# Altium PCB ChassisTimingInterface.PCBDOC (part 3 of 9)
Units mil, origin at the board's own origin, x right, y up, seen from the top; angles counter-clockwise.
Board outline 7007.87 x 4368.85 mil, 10 copper layers (Top Layer, Int1 (GND), Int2 (Sign), Int3 (Sign), Int4 (PWR), Int5 (GND), Int6 (Sign), Int7 (Sign), Int8 (GND), Bottom Layer), stack 54.89 mil thick; 537 components, 525 nets, 2288 pads, 1306 vias.
Unrouted connection lines stored in the file: 373.
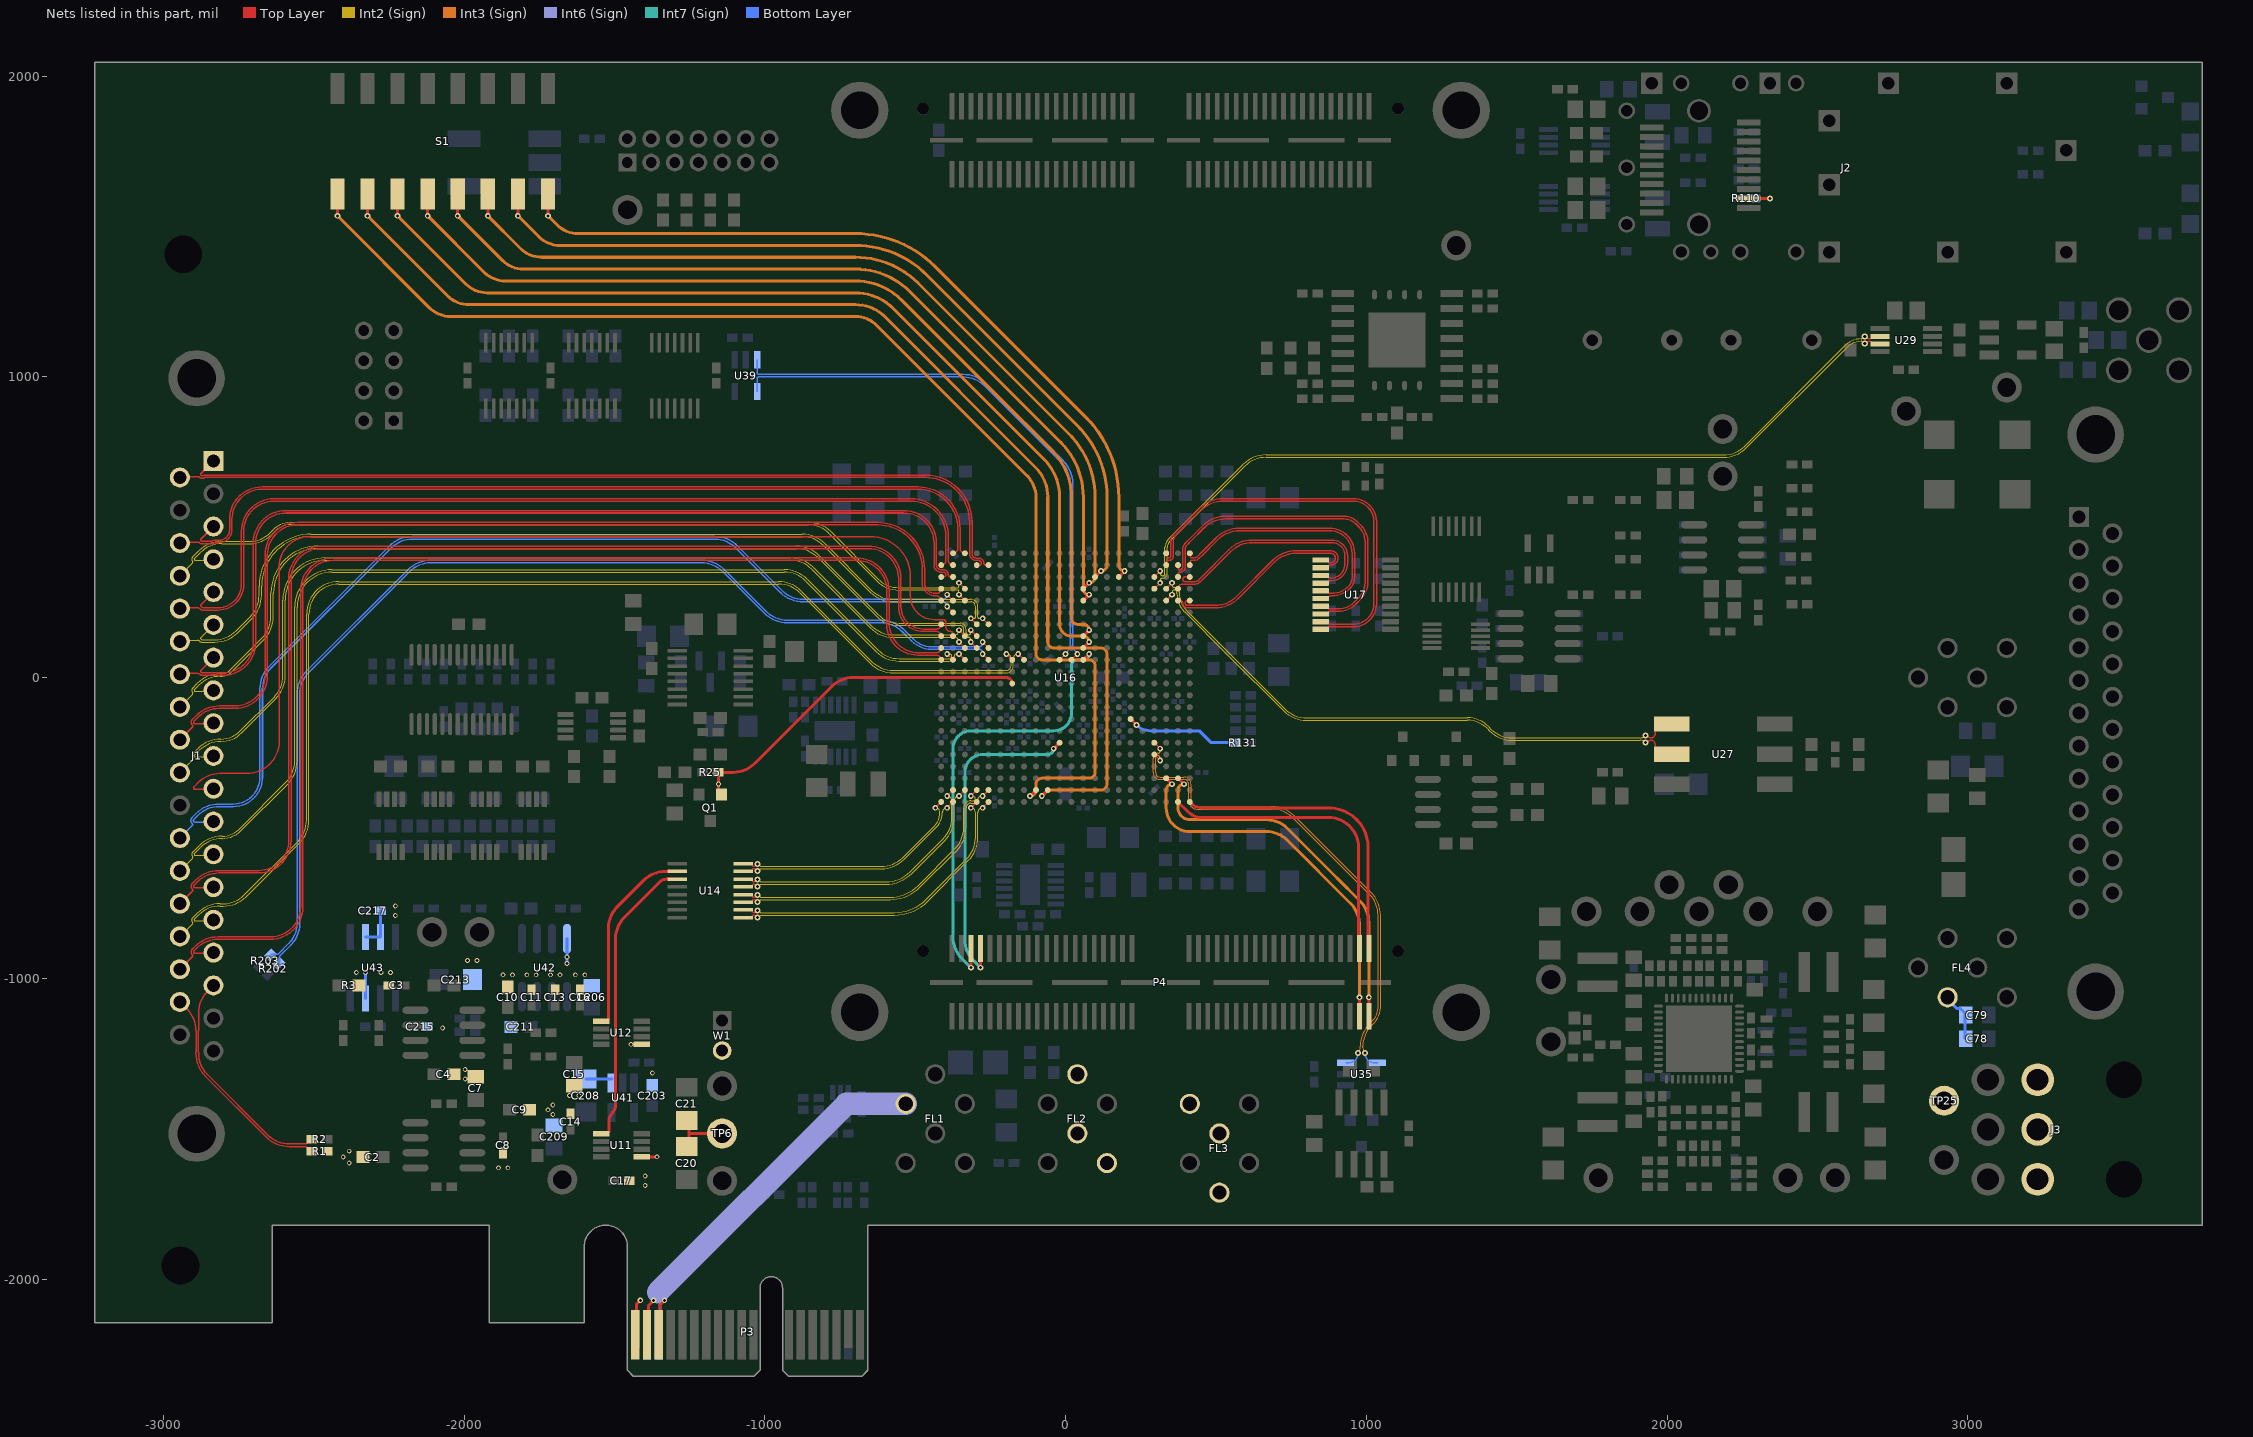
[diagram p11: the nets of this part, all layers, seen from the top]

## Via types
v1: diameter 19, hole 10, Top Layer to Bottom Layer, tented both sides, 667 vias
v2: diameter 20, hole 10, Top Layer to Bottom Layer, tented both sides, 248 vias
v3: diameter 16, hole 10, Top Layer to Bottom Layer, tented both sides, 191 vias
v4: diameter 12, hole 6, Top Layer to Bottom Layer, tented both sides, 85 vias
v5: diameter 19.68, hole 10, Top Layer to Bottom Layer, tented both sides, 50 vias
v6: diameter 17.72, hole 10, Top Layer to Bottom Layer, tented both sides, 19 vias
v7: diameter 19, hole 10, Top Layer to Bottom Layer, 15 vias
v8: diameter 23.62, hole 10, Top Layer to Bottom Layer, tented both sides, 14 vias
v9: diameter 20, hole 10, Top Layer to Bottom Layer, 11 vias
v10: diameter 16, hole 10, Top Layer to Bottom Layer, 3 vias
v11: diameter 22, hole 12, Top Layer to Bottom Layer, tented both sides, 2 vias
v12: diameter 19.02, hole 10, Top Layer to Bottom Layer, tented both sides, 1 vias

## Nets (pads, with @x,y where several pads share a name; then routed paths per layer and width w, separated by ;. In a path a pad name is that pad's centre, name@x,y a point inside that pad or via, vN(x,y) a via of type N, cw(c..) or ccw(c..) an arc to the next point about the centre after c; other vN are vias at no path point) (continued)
BACKPLANE.CLK1_P: J1.11 U16.B15 | length 3536.1
  Top Layer w5: J1.11@-2832.87,-369.88 cw(c-2837.97,-364.78) -2837.97,-371.99 -2894.34,-371.99 cw(c-2894.34,-366.99) -2897.88,-370.53 cw(c-2894.34,-366.99) -2899.34,-366.99 cw(c-2894.34,-366.99) -2897.88,-363.46 -2882.6,-348.19 cw(c-2811.89,-418.9) -2811.89,-318.9 -2722.17,-318.9 ccw(c-2722.17,-210.9) -2614.17,-210.9 -2614.17,368.5 cw(c-2514.17,368.5) -2514.17,468.5 -647.75,468.5 cw(c-647.75,336.5) -515.75,336.5 -515.75,271.53 ccw(c-436.92,271.53) -436.92,192.7 -406.92,192.7 cw(c-406.92,183.55) -397.77,183.55 -397.77,168.53 ccw(c-382.72,168.53) -382.72,153.48 cw(c-382.72,144.78) -374.02,144.78 U16.B15@-374.02,137.8
BACKPLANE.CLK2_N: J1.29 U16.C15 | length 3214.3
  Top Layer w5: v1(-354.33,157.48) U16.C15@-334.65,137.8
  Int2 (Sign) w3: J1.29@-2944.69,-315.35 -2902.12,-272.79 ccw(c-2904.24,-270.67) -2901.24,-270.67 ccw(c-2904.24,-270.67) -2902.12,-268.54 ; -2905.34,-260.8 ccw(c-2894.42,-260.8) -2902.14,-268.52 ; -2905.34,-260.76 cw(c-2894.36,-260.76) -2902.13,-253 -2885.33,-236.2 cw(c-2809.03,-312.5) -2809.03,-204.6 ccw(c-2809.03,-114.05) -2745.01,-178.08 -2631.78,-64.85 ccw(c-2702.49,5.86) -2602.49,5.86 -2602.49,257.76 cw(c-2462.49,257.76) -2462.49,397.76 -914.9,397.76 cw(c-914.9,289.85) -838.6,366.16 -643.53,171.09 ccw(c-572.82,241.8) -572.82,141.8 -536.42,141.8 -370.02,141.8 ccw(c-370.02,157.48) v1(-354.33,157.48)
BACKPLANE.CLK2_P: J1.10 U16.C14 | length 3195.2
  Top Layer w5: v1(-354.33,118.11) U16.C14@-334.65,98.43
  Int2 (Sign) w3: J1.10@-2832.87,-260.83 cw(c-2839.97,-253.73) -2839.97,-263.77 -2894.34,-263.77 cw(c-2894.34,-260.77) -2896.46,-262.89 cw(c-2894.34,-260.77) -2897.34,-260.77 cw(c-2894.34,-260.77) -2896.46,-258.65 -2879.7,-241.89 cw(c-2808.99,-312.6) -2808.99,-212.6 ccw(c-2808.99,-114.15) -2739.38,-183.76 -2626.09,-70.48 ccw(c-2702.39,5.82) -2594.49,5.82 -2594.49,257.76 cw(c-2462.49,257.76) -2462.49,389.76 -914.94,389.76 cw(c-914.94,289.76) -844.23,360.47 -649.17,165.41 ccw(c-572.84,241.74) -572.99,133.8 ccw(c-572.84,241.74) -572.84,133.8 -536.42,133.8 -370.02,133.8 cw(c-370.02,118.11) v1(-354.33,118.11)
BACKPLANE.CLK3_N: J1.28 U16.A19 | length 3274.8
  Top Layer w5: J1.28@-2944.69,-206.3 -2903.53,-165.15 ccw(c-2907.07,-161.61) -2902.07,-161.61 ccw(c-2907.07,-161.61) -2903.53,-158.08 ; -2903.57,-158.04 cw(c-2894.46,-148.93) -2907.34,-148.93 -2907.34,-148.81 cw(c-2894.51,-148.81) -2903.58,-139.74 -2889.81,-125.97 cw(c-2813.51,-202.26) -2813.51,-94.36 -2761.54,-94.36 ccw(c-2761.54,5.64) -2661.54,5.64 -2661.54,407.87 cw(c-2553.54,407.87) -2553.54,515.87 -624.38,515.87 cw(c-624.38,359.87) -468.38,359.87 -468.38,314.93 ccw(c-433.04,314.93) -433.04,279.59 -429.07,279.59 ccw(c-429.07,295.28) U16.A19@-413.39,295.28
BACKPLANE.CLK3_P: J1.9 U16.A18 | length 3255.9
  Top Layer w5: J1.9@-2832.87,-151.77 cw(c-2837.97,-146.67) -2837.97,-153.88 -2894.34,-153.88 cw(c-2894.34,-148.88) -2897.88,-152.42 cw(c-2894.34,-148.88) -2899.34,-148.88 cw(c-2894.34,-148.88) -2897.88,-145.35 -2884.18,-131.65 cw(c-2813.47,-202.36) -2813.47,-102.36 -2761.54,-102.36 ccw(c-2761.54,5.64) -2653.54,5.64 -2653.54,407.87 cw(c-2553.54,407.87) -2553.54,507.87 -624.38,507.87 cw(c-624.38,359.87) -476.38,359.87 -476.38,314.93 ccw(c-433.04,314.93) -433.04,271.59 -429.07,271.59 cw(c-429.07,255.91) U16.A18@-413.39,255.91
BACKPLANE.CLK4_N: J1.27 U16.D15 | length 3113.3
  Top Layer w5: v1(-314.96,157.48) U16.D15@-295.28,137.8
  Int2 (Sign) w3: J1.27@-2944.69,-97.24 -2902.12,-54.68 ccw(c-2904.24,-52.56) -2901.24,-52.56 ccw(c-2904.24,-52.56) -2902.12,-50.43 ; -2905.34,-42.69 ccw(c-2894.42,-42.69) -2902.14,-50.41 ; -2905.34,-42.65 cw(c-2894.36,-42.65) -2902.13,-34.89 -2886.91,-19.67 cw(c-2810.61,-95.96) -2810.61,11.94 ccw(c-2810.61,58.76) -2777.5,25.65 -2671.15,132 ccw(c-2741.86,202.71) -2641.86,202.71 -2641.86,281.13 cw(c-2485.86,281.13) -2485.86,437.13 -895.22,437.13 cw(c-895.22,329.22) -818.91,405.53 -623.9,210.52 ccw(c-553.19,281.23) -553.19,181.23 -536.42,181.23 -350.52,181.23 cw(c-350.52,161.42) -330.71,161.42 -330.71,149.67 ccw(c-322.83,149.67) -322.83,141.8 ccw(c-322.83,149.67) -314.96,149.67 v1(-314.96,157.48)
BACKPLANE.CLK4_P: J1.8 U16.D14 | length 3094.1
  Top Layer w5: v1(-314.96,118.11) U16.D14@-295.28,98.43
  Int2 (Sign) w3: J1.8@-2832.87,-42.72 cw(c-2839.97,-35.62) -2839.97,-45.66 -2894.34,-45.66 cw(c-2894.34,-42.66) -2896.46,-44.78 cw(c-2894.34,-42.66) -2897.34,-42.66 cw(c-2894.34,-42.66) -2896.46,-40.53 -2881.28,-25.35 cw(c-2810.57,-96.06) -2810.57,3.94 ; -2810.52,3.94 ccw(c-2810.52,58.56) -2771.9,19.94 -2665.39,126.45 ccw(c-2741.5,202.57) -2633.86,202.57 -2633.86,281.13 cw(c-2485.86,281.13) -2485.86,429.13 -1354.33,429.13 -895.25,429.13 cw(c-895.25,329.13) -824.54,399.84 -629.54,204.84 ccw(c-553.22,281.17) -553.36,173.23 ccw(c-553.22,281.17) -553.22,173.23 -536.42,173.23 -350.52,173.23 cw(c-350.52,161.42) -338.71,161.42 -338.71,149.67 ccw(c-322.83,149.67) -322.83,133.8 cw(c-322.83,125.92) -314.96,125.92 v1(-314.96,118.11)
BACKPLANE.CLK5_N: J1.26 U16.A20 | length 3167.9
  Top Layer w5: J1.26@-2944.69,11.81 cw(c-2939.59,6.71) -2939.59,13.92 -2885.51,13.92 cw(c-2885.51,3.38) -2878.06,10.84 ccw(c-2870.61,18.29) -2870.61,7.75 -2800.91,7.75 ccw(c-2800.91,115.75) -2692.91,115.75 -2692.91,447.24 cw(c-2592.91,447.24) -2592.91,547.24 -537.13,547.24 cw(c-537.13,447.24) -437.13,447.24 -437.13,374.02 ccw(c-413.45,374.02) -413.45,350.33 -405.57,350.33 cw(c-405.57,342.46) -397.7,342.46 cw(c-405.51,342.46) -405.51,334.65 U16.A20@-413.39,334.65
BACKPLANE.CLK5_P: J1.7 U16.B20 | length 3174.3
  Top Layer w5: J1.7@-2832.87,66.34 -2874.03,25.19 ccw(c-2870.49,21.65) -2875.49,21.65 ccw(c-2870.49,21.65) -2874.03,18.12 ccw(c-2868.31,23.83) -2868.31,15.75 -2800.91,15.75 ccw(c-2800.91,115.75) -2700.91,115.75 -2700.91,447.24 cw(c-2592.91,447.24) -2592.91,555.24 -537.13,555.24 cw(c-537.13,447.24) -429.13,447.24 -429.13,374.02 ccw(c-413.45,374.02) -413.45,358.33 -405.57,358.33 cw(c-405.57,342.46) -389.7,342.46 ccw(c-381.89,342.46) -381.89,334.65 U16.B20@-374.02,334.65
BACKPLANE.CLK6_N: J1.25 U16.D16 | length 3024.6
  Top Layer w5: v1(-314.96,196.85) U16.D16@-295.28,177.17
  Int2 (Sign) w3: J1.25@-2944.69,120.87 cw(c-2937.59,113.77) -2937.59,123.81 -2886.09,123.81 cw(c-2886.09,113.87) -2879.07,120.9 ccw(c-2872.04,127.92) -2872.04,117.98 -2828.78,117.98 ccw(c-2828.78,225.89) -2752.48,149.59 -2704.83,197.24 ccw(c-2781.13,273.54) -2673.23,273.54 -2673.23,304.5 cw(c-2509.23,304.5) -2509.23,468.5 -875.57,468.5 cw(c-875.57,368.5) -804.86,439.21 -649.23,283.58 ccw(c-572.9,359.91) -573.05,251.97 ccw(c-572.9,359.91) -572.9,251.97 -536.42,251.97 -314.96,251.97 cw(c-314.96,236.28) -299.28,236.28 -299.28,200.79 cw(c-303.21,200.79) -303.21,196.85 v1(-314.96,196.85)
BACKPLANE.CLK6_P: J1.6 U16.E16 | length 3031.2
  Top Layer w5: v1(-275.59,196.85) U16.E16@-255.91,177.17
  Int2 (Sign) w3: J1.6@-2832.87,175.39 -2875.44,132.83 ccw(c-2873.32,130.71) -2876.32,130.71 ccw(c-2873.32,130.71) -2875.44,128.58 ccw(c-2869.16,134.86) -2869.16,125.98 -2828.82,125.98 ccw(c-2828.82,225.98) -2758.11,155.27 -2710.52,202.87 ccw(c-2781.23,273.58) -2681.23,273.58 -2681.23,304.5 cw(c-2509.23,304.5) -2509.23,476.5 -875.53,476.5 cw(c-875.53,368.59) -799.23,444.9 -643.59,289.26 ccw(c-572.88,359.97) -572.88,259.97 -536.42,259.97 -314.96,259.97 cw(c-314.96,236.28) -291.28,236.28 -291.28,200.79 ccw(c-287.34,200.79) -287.34,196.85 v1(-275.59,196.85)
BACKPLANE.CLK7_N: J1.24 U16.A21 | length 3003.7
  Top Layer w5: J1.24@-2944.69,229.92 cw(c-2939.59,224.82) -2939.59,232.03 -2886.63,232.03 cw(c-2886.63,218.8) -2877.27,228.16 ccw(c-2867.92,237.51) -2867.92,224.28 -2818.86,224.28 ccw(c-2818.86,310.98) -2732.16,310.98 -2732.16,486.68 cw(c-2632.16,486.68) -2632.16,586.68 -513.7,586.68 cw(c-513.7,470.68) -397.7,470.68 -397.7,452.76 -397.7,389.7 cw(c-413.39,389.7) U16.A21@-413.39,374.02
BACKPLANE.CLK7_P: J1.5 U16.B21 | length 3010.1
  Top Layer w5: J1.5@-2832.87,284.45 -2874.03,243.3 ccw(c-2870.49,239.76) -2875.49,239.76 ccw(c-2870.49,239.76) -2874.03,236.23 ccw(c-2864.51,245.74) -2864.51,232.28 -2818.9,232.28 ccw(c-2818.9,311.02) -2740.16,311.02 -2740.16,486.68 cw(c-2632.16,486.68) -2632.16,594.68 -513.7,594.68 cw(c-513.7,470.68) -389.7,470.68 -389.7,452.76 -389.7,389.7 ccw(c-374.02,389.7) U16.B21@-374.02,374.02
BACKPLANE.CLK8_N: J1.23 U16.C19 | length 2788.3
  Top Layer w5: v1(-354.33,314.96) U16.C19@-334.65,295.28
  Int2 (Sign) w3: J1.23@-2944.69,338.98 -2902.12,381.54 ccw(c-2904.24,383.66) -2901.24,383.66 ccw(c-2904.24,383.66) -2902.12,385.79 ; -2905.34,393.53 ccw(c-2894.42,393.53) -2902.14,385.81 ; -2905.34,393.57 cw(c-2894.36,393.57) -2902.13,401.34 -2882.18,421.28 cw(c-2805.88,344.98) -2805.88,452.88 -2714.52,452.88 ccw(c-2714.52,552.88) -2643.81,482.17 -2633.83,492.15 cw(c-2576.56,434.88) -2576.56,515.87 -855.79,515.87 cw(c-855.79,408.11) -779.59,484.31 -623.78,328.5 ccw(c-553.07,399.21) -553.07,299.21 -549.1,299.21 -549.03,299.28 -536.42,299.28 -356.09,299.28 -354.33,301.03 v1(-354.33,314.96)
BACKPLANE.CLK8_P: J1.4 U16.C18 | length 2769.1
  Top Layer w5: v1(-354.33,275.59) U16.C18@-334.65,255.91
  Int2 (Sign) w3: J1.4@-2832.87,393.5 cw(c-2839.97,400.6) -2839.97,390.56 -2894.34,390.56 cw(c-2894.34,393.56) -2896.46,391.44 cw(c-2894.34,393.56) -2897.34,393.56 cw(c-2894.34,393.56) -2896.46,395.69 -2876.55,415.59 cw(c-2805.84,344.88) -2805.84,444.88 -2714.48,444.88 ccw(c-2714.48,552.78) -2638.19,476.49 -2628.2,486.47 cw(c-2576.53,434.79) -2576.53,507.87 -855.88,507.87 cw(c-855.88,407.87) -785.17,478.58 -629.42,322.83 ccw(c-553.09,399.16) -553.09,291.21 -545.15,291.21 -545.09,291.28 -536.42,291.28 -356.09,291.28 -354.33,289.52 v1(-354.33,275.59)
BACKPLANE.CLK9_N: J1.22 U16.B22 | length 2870.1
  Top Layer w5: J1.22@-2944.69,448.03 cw(c-2939.59,442.93) -2939.59,450.14 -2884.88,450.14 cw(c-2884.88,441.14) -2878.51,447.51 ccw(c-2872.15,453.87) -2872.15,444.87 -2840.36,444.87 ccw(c-2840.36,456.23) -2832.33,448.2 ; -2832.31,448.21 cw(c-2830.86,446.76) -2830.86,448.82 -2814.83,448.82 ccw(c-2814.83,492.13) -2771.53,492.13 -2771.53,526.05 cw(c-2671.53,526.05) -2671.53,626.05 -490.33,626.05 cw(c-490.33,494.05) -358.33,494.05 -358.33,452.76 -358.33,429.07 cw(c-374.02,429.07) U16.B22@-374.02,413.39
BACKPLANE.CLK9_P: J1.3 U16.C22 | length 2876.4
  Top Layer w5: -2837.97,453.87 cw(c-2840.39,456.29) -2840.39,452.87 -2870.49,452.87 cw(c-2870.49,457.87) -2874.03,454.34 cw(c-2870.49,457.87) -2875.49,457.87 cw(c-2870.49,457.87) -2874.03,461.41 J1.3@-2832.87,502.56 ; -2837.94,453.9 cw(c-2830.89,446.85) -2830.89,456.82 -2814.83,456.82 ccw(c-2814.83,492.13) -2779.53,492.13 -2779.53,526.05 cw(c-2671.53,526.05) -2671.53,634.05 -490.33,634.05 cw(c-490.33,494.05) -350.33,494.05 -350.33,452.76 -350.33,429.07 ccw(c-334.65,429.07) U16.C22@-334.65,413.39
BACKPLANE.CS_N: J1.32 U16.B13 | length 3492.2
  Top Layer w5: v1(-393.7,78.74) U16.B13@-374.02,59.06
  Int2 (Sign) w3: J1.32@-2944.69,-642.52 -2902.12,-599.95 ccw(c-2904.24,-597.83) -2901.24,-597.83 ccw(c-2904.24,-597.83) -2902.12,-595.71 ; -2902.14,-595.69 cw(c-2894.42,-587.96) -2905.34,-587.96 cw(c-2894.36,-587.92) -2902.13,-580.16 -2881,-559.04 cw(c-2804.7,-635.33) -2804.7,-527.43 ccw(c-2804.7,-447.34) -2748.07,-503.97 -2592.41,-348.31 ccw(c-2663.12,-277.6) -2563.12,-277.6 -2563.12,234.39 cw(c-2439.12,234.39) -2439.12,358.39 -934.59,358.39 cw(c-934.59,250.48) -858.28,326.79 -623.78,92.28 ccw(c-553.07,162.99) -553.07,62.99 -536.42,62.99 -385.89,62.99 ccw(c-385.89,70.87) -378.02,70.87 ccw(c-385.89,70.87) -385.89,78.74 v1(-393.7,78.74)
BACKPLANE.CS_P: J1.13 U16.C13 | length 3485.6
  Top Layer w5: v1(-354.33,78.74) U16.C13@-334.65,59.06
  Int2 (Sign) w3: J1.13@-2832.87,-587.99 cw(c-2839.97,-580.89) -2839.97,-590.93 -2894.34,-590.93 cw(c-2894.34,-587.93) -2896.46,-590.05 cw(c-2894.34,-587.93) -2897.34,-587.93 cw(c-2894.34,-587.93) -2896.46,-585.81 -2875.37,-564.72 cw(c-2804.66,-635.43) -2804.66,-535.43 ccw(c-2804.66,-447.44) -2742.44,-509.66 -2586.72,-353.94 ccw(c-2663.02,-277.64) -2555.12,-277.64 -2555.12,234.39 cw(c-2439.12,234.39) -2439.12,350.39 -934.62,350.39 cw(c-934.62,250.39) -863.91,321.1 -629.42,86.61 ccw(c-553.09,162.93) -553.09,54.99 -536.42,54.99 -385.89,54.99 ccw(c-385.89,70.87) -370.02,70.87 cw(c-362.14,70.87) -362.14,78.74 v1(-354.33,78.74)
BACKPLANE.DIN_N: J1.35 U16.A14 | length 3995
  Top Layer w5: J1.35@-2944.69,-969.68 -2903.53,-928.53 ccw(c-2907.07,-925) -2902.07,-925 ccw(c-2907.07,-925) -2903.53,-921.46 cw(c-2894.46,-912.32) -2907.34,-912.32 -2907.34,-912.2 cw(c-2894.51,-912.2) -2903.58,-903.13 -2894.14,-893.68 cw(c-2817.84,-969.98) -2817.84,-862.08 -2643.43,-862.08 ccw(c-2643.43,-762.08) -2543.43,-762.08 -2543.43,289.76 cw(c-2435.43,289.76) -2435.43,397.76 -694.49,397.76 cw(c-694.49,289.76) -586.49,289.76 -586.49,181.04 ccw(c-488.19,181.04) -488.19,82.74 -452.76,82.74 -429.07,82.74 ccw(c-429.07,98.43) U16.A14@-413.39,98.43
BACKPLANE.DIN_P: J1.16 U16.A13 | length 3977.4
  Top Layer w5: J1.16@-2832.87,-915.16 cw(c-2837.97,-910.06) -2837.97,-917.27 -2894.34,-917.27 cw(c-2894.34,-912.27) -2897.88,-915.8 cw(c-2894.34,-912.27) -2899.34,-912.27 cw(c-2894.34,-912.27) -2897.88,-908.73 -2888.51,-899.37 cw(c-2817.8,-970.08) -2817.8,-870.08 -2643.43,-870.08 ccw(c-2643.43,-762.08) -2535.43,-762.08 -2535.43,289.76 cw(c-2435.43,289.76) -2435.43,389.76 -694.49,389.76 cw(c-694.49,289.76) -594.49,289.76 -594.49,177.73 ccw(c-491.5,177.73) -491.5,74.74 -452.76,74.74 -429.07,74.74 cw(c-429.07,59.06) U16.A13@-413.39,59.06
BACKPLANE.DOUT_N: J1.34 U16.G13 | length 3894
  Top Layer w5: v1(-196.85,78.74) U16.G13@-177.17,59.06
  Int2 (Sign) w3: J1.34@-2944.69,-860.63 -2902.12,-818.06 ccw(c-2904.24,-815.94) -2901.24,-815.94 ccw(c-2904.24,-815.94) -2902.12,-813.82 ; -2905.34,-806.07 ccw(c-2894.42,-806.07) -2902.14,-813.8 ; -2905.34,-806.03 cw(c-2894.36,-806.03) -2902.13,-798.27 -2887.3,-783.45 cw(c-2811,-859.74) -2811,-751.84 -2801.14,-751.84 ccw(c-2801.14,-651.84) -2730.43,-722.55 -2553.04,-545.16 ccw(c-2623.75,-474.45) -2523.75,-474.45 -2523.75,211.02 cw(c-2415.75,211.02) -2415.75,319.02 -954.25,319.02 cw(c-954.25,211.17) -877.98,287.43 -643.46,52.91 ccw(c-572.75,123.62) -572.75,23.62 -536.42,23.62 -196.91,23.62 ccw(c-196.91,39.37) -181.17,39.37 -181.17,63.06 ccw(c-196.85,63.06) v1(-196.85,78.74)
BACKPLANE.DOUT_P: J1.15 U16.H13 | length 3887.4
  Top Layer w5: v1(-157.48,78.74) U16.H13@-137.8,59.06
  Int2 (Sign) w3: J1.15@-2832.87,-806.1 cw(c-2839.97,-799) -2839.97,-809.04 -2894.34,-809.04 cw(c-2894.34,-806.04) -2896.46,-808.16 cw(c-2894.34,-806.04) -2897.34,-806.04 cw(c-2894.34,-806.04) -2896.46,-803.92 -2881.67,-789.13 cw(c-2810.96,-859.84) -2810.96,-759.84 -2801.1,-759.84 ccw(c-2801.1,-651.94) -2724.8,-728.24 -2547.35,-550.79 ccw(c-2623.65,-474.49) -2515.75,-474.49 -2515.75,211.02 cw(c-2415.75,211.02) -2415.75,311.02 -954.31,311.02 cw(c-954.31,211.02) -883.6,281.73 -649.1,47.24 ccw(c-572.78,123.56) -572.78,15.62 -536.42,15.62 -196.91,15.62 ccw(c-196.91,39.37) -173.17,39.37 -173.17,63.06 cw(c-157.48,63.06) v1(-157.48,78.74)
BACKPLANE.SCLK_N: J1.33 U16.A16 | length 3785.6
  Top Layer w5: J1.33@-2944.69,-751.57 -2903.53,-710.42 ccw(c-2907.07,-706.89) -2902.07,-706.89 ccw(c-2907.07,-706.89) -2903.53,-703.35 ; -2903.57,-703.32 cw(c-2894.46,-694.21) -2907.34,-694.21 -2907.34,-694.09 cw(c-2894.51,-694.09) -2903.58,-685.02 -2891.78,-673.21 cw(c-2815.48,-749.51) -2815.48,-641.61 -2682.8,-641.61 ccw(c-2682.8,-541.61) -2582.8,-541.61 -2582.8,329.13 cw(c-2474.8,329.13) -2474.8,437.13 -655.24,437.13 cw(c-655.24,329.13) -547.24,329.13 -547.24,236.22 ccw(c-472.5,236.22) -472.5,161.48 -452.76,161.48 -429.07,161.48 ccw(c-429.07,177.17) U16.A16@-413.39,177.17
BACKPLANE.SCLK_P: J1.14 U16.A15 | length 3766.6
  Top Layer w5: J1.14@-2832.87,-697.05 cw(c-2837.97,-691.95) -2837.97,-699.16 -2894.34,-699.16 cw(c-2894.34,-694.16) -2897.88,-697.69 cw(c-2894.34,-694.16) -2899.34,-694.16 cw(c-2894.34,-694.16) -2897.88,-690.62 -2886.15,-678.9 cw(c-2815.44,-749.61) -2815.44,-649.61 -2682.8,-649.61 ccw(c-2682.8,-541.61) -2574.8,-541.61 -2574.8,329.13 cw(c-2474.8,329.13) -2474.8,429.13 -655.24,429.13 cw(c-655.24,329.13) -555.24,329.13 -555.24,236.22 ccw(c-472.5,236.22) -472.5,153.48 -452.76,153.48 -429.07,153.48 cw(c-429.07,137.8) U16.A15@-413.39,137.8
BACKPLANE.X1_N: R203.1 U16.E14 | length 3534
  Top Layer w5: v1(-275.59,118.11) U16.E14@-255.91,98.43
  Bottom Layer w5: R203.1@-2643.32,-922.85 cw(c-2636.6,-929.57) -2636.6,-920.07 -2624.94,-920.07 ccw(c-2623.34,-918.47) -2623.34,-920.73 ccw(c-2623.34,-911.99) -2617.16,-918.17 -2581.78,-882.79 ccw(c-2646.15,-818.42) -2555.12,-818.42 -2555.12,-54.57 cw(c-2446.81,-54.57) -2523.39,22.01 -2186.64,358.77 cw(c-2110.05,282.18) -2110.05,390.49 -1210.62,390.49 cw(c-1210.62,282.1) -1133.98,358.74 -995.11,219.87 ccw(c-924.4,290.58) -924.4,190.58 -613.43,190.58 cw(c-613.43,82.19) -536.79,158.83 -505.99,128.04 ccw(c-444.88,189.15) -444.88,102.73 -287.4,102.73 ccw(c-287.4,114.54) -275.59,114.54 v1(-275.59,118.11)
BACKPLANE.X1_P: R202.1 U16.E13 | length 3527.2
  Top Layer w5: v1(-275.59,78.74) U16.E13@-255.91,59.06
  Bottom Layer w5: R202.1@-2615.76,-950.41 ccw(c-2622.48,-943.69) -2612.98,-943.69 -2612.98,-932.03 cw(c-2611.38,-930.43) -2613.64,-930.43 cw(c-2604.9,-930.43) -2611.08,-924.25 -2575.56,-888.73 ccw(c-2645.67,-818.62) -2546.52,-818.62 -2546.52,-54.69 cw(c-2446.52,-54.69) -2517.23,16.02 -2180.64,352.6 cw(c-2109.93,281.89) -2109.93,381.89 -1210.71,381.89 cw(c-1210.71,281.89) -1140,352.6 -1001.16,213.76 ccw(c-924.44,290.47) -924.44,181.98 -613.52,181.98 cw(c-613.52,81.98) -542.81,152.69 -511.97,121.86 ccw(c-445.02,188.82) -445.02,94.13 -287.4,94.13 cw(c-287.4,82.32) -275.59,82.32 v1(-275.59,78.74)
BACKPLANE.X3_N: J1.31 U16.B18 | length 3298.2
  Top Layer w5: v1(-393.7,275.59) U16.B18@-374.02,255.91
  Bottom Layer w5: J1.31@-2944.88,-533.65 -2904.23,-492.99 ccw(c-2908.11,-489.1) -2902.61,-489.1 ccw(c-2908.11,-489.1) -2904.23,-485.21 ; -2904.25,-485.18 cw(c-2894.35,-475.28) -2908.36,-475.28 -2908.36,-475.22 cw(c-2894.31,-475.22) -2904.24,-465.29 -2891.21,-452.26 cw(c-2814.62,-528.85) -2814.62,-420.53 -2767.72,-420.53 ccw(c-2767.72,-331.47) -2678.65,-331.47 -2678.65,-38.1 cw(c-2570.34,-38.1) -2646.93,38.48 -2247.9,437.51 cw(c-2171.32,360.92) -2171.32,469.23 -1167.01,469.23 cw(c-1167.01,360.84) -1090.37,437.48 -942.38,289.5 ccw(c-871.67,360.21) -871.67,260.21 -452.76,260.21 -409.09,260.21 ccw(c-409.09,275.59) v1(-393.7,275.59)
BACKPLANE.X3_P: J1.12 U16.B17 | length 3277.8
  Top Layer w5: v1(-393.7,236.22) U16.B17@-374.02,216.54
  Bottom Layer w5: J1.12@-2833.07,-478.65 cw(c-2838.13,-473.59) -2838.13,-480.74 -2894.26,-480.74 cw(c-2894.26,-475.24) -2898.14,-479.13 cw(c-2894.26,-475.24) -2899.76,-475.24 cw(c-2894.26,-475.24) -2898.14,-471.35 -2885.22,-458.42 cw(c-2814.51,-529.13) -2814.51,-429.13 -2767.72,-429.13 ccw(c-2767.72,-331.47) -2670.05,-331.47 -2670.05,-38.22 cw(c-2570.05,-38.22) -2640.76,32.49 -2241.91,431.34 cw(c-2171.2,360.63) -2171.2,460.63 -1167.1,460.63 cw(c-1167.1,360.63) -1096.39,431.34 -948.43,283.38 ccw(c-871.72,360.09) -871.72,251.61 -452.76,251.61 -409.09,251.61 cw(c-409.09,236.22) v1(-393.7,236.22)
BACKPLANE.X5_N: J1.20 U16.D21 | length 2895
  Top Layer w5: J1.20@-2944.69,666.14 cw(c-2939.59,661.04) -2939.59,668.25 -2884.88,668.25 cw(c-2884.88,659.25) -2878.51,665.62 ccw(c-2872.15,671.98) -2872.15,662.98 -2866.86,662.98 ccw(c-2866.86,667.21) -2863.87,664.22 cw(c-2860.88,661.23) -2860.88,665.46 -466.92,665.46 cw(c-466.92,517.46) -318.92,517.46 -318.92,452.76 -318.92,412.07 ccw(c-296.32,412.07) -296.32,389.47 -288.54,389.47 cw(c-288.54,380.52) -279.59,380.52 cw(c-286.1,380.52) -286.1,374.02 U16.D21@-295.28,374.02
BACKPLANE.X5_P: J1.1 U16.E21 | length 2901.3
  Top Layer w5: J1.1@-2832.87,720.55 -2863.84,689.59 -2863.96,689.59 -2874.03,679.52 ccw(c-2870.49,675.98) -2875.49,675.98 ccw(c-2870.49,675.98) -2874.03,672.45 ccw(c-2870.49,675.98) -2870.49,670.98 -2870.17,670.98 ccw(c-2870.17,675.21) -2867.18,672.22 cw(c-2864.19,669.23) -2864.19,673.46 -466.92,673.46 cw(c-466.92,517.46) -310.92,517.46 -310.92,452.76 -310.92,412.07 ccw(c-296.32,412.07) -296.32,397.47 -288.54,397.47 cw(c-288.54,380.52) -271.59,380.52 ccw(c-265.08,380.52) -265.08,374.02 U16.E21@-255.91,374.02
BGND: C2.1 C3.1 C4.1 C7.2 C8.2 C9.2 C10.2 C11.1 C13.2 C14.2 C15.2 C16.2 C17.2 C20.1 C21.1 C203.1 C206.2 C208.1 C209.2 C211.1 C213.1 C215.1 C217.1 FL2.4 FL2.5 FL2.6 FL3.4 FL3.5 FL3.6 R1.1 R3.1 TP6.1 U11.5 U12.5 U41.1 U42.4 U43.3 U43.6 U43.7 W1.2 | length 679.8
  Top Layer w10: v3(-1445.01,-1219.49) U12.5@-1409.45,-1219.49 ; U11.5@-1409.45,-1593.5 v3(-1358.27,-1593.5) ; C20.1@-1259.84,-1559.06 -1251.97,-1551.18 -1251.97,-1515.75 ; C21.1@-1259.84,-1472.44 -1251.97,-1480.31 -1251.97,-1515.75 ; TP6.1@-1141.73,-1515.75 -1251.97,-1515.75
  Bottom Layer w10: v3@-2330.71,-984.25 -2328.15,-984.25 U43.3@-2328.15,-1066.93 ; U43.6@-2328.15,-862.2 U43.7@-2279.53,-862.2 ; U43.7@-2278.15,-862.2 -2278.15,-776.18 C217.1@-2277.56,-775.59 ; v3(-1657.48,-950.41) -1657.48,-868.31 U42.4@-1657.28,-868.11 ; C208.1@-1594.49,-1334.65 U41.1@-1507.87,-1334.65
  other v3: -1397.64,-1688.98 -1397.64,-1657.48 -1885.83,-1629.92 -1854.33,-1629.92 -1704.72,-1452.76 -1720.47,-1437.01 -1704.72,-1421.26 -1649.61,-1389.76 -1618.11,-1389.76 -1996.06,-1334.65 -1374.02,-1314.96 -1996.06,-1303.15 -2070.87,-1165.35 -1870.08,-988.19 -1838.58,-988.19 -1791.34,-988.19 -1759.84,-988.19 -1712.6,-988.19 -1681.1,-988.19 -1629.92,-988.19 -1598.43,-988.19 -2358.27,-980.31 -2326.77,-980.31 -2275.59,-980.31 -2244.09,-980.31 -1988.19,-940.94 -1956.69,-940.94 -1657.28,-929.57 -2228.35,-791.34 -2228.35,-759.84
  other v10: -2381.89,-1614.17 -2401.57,-1594.49 -2381.89,-1574.8
BUS12V: FL1.1 P3.A2 P3.A3 P3.B1 P3.B2 P3.B3 | length 1695.5
  Top Layer w10: P3.B1@-1431.1,-2185.04 -1426.28,-2180.22 -1426.28,-2083.27 v6(-1413.63,-2070.62) ; P3.B2@-1391.73,-2185.04 -1386.91,-2180.22 -1386.91,-2088.19 v6(-1369.34,-2070.62) ; P3.B3@-1352.36,-2185.04 -1347.54,-2180.22 -1347.54,-2084.5 v6(-1333.66,-2070.62)
  Int6 (Sign) w75: -1354.33,-2043.31 -728.35,-1417.32 FL1.1@-531.5,-1417.32
  Bottom Layer w10: P3.A2@-1391.73,-2185.04 -1386.91,-2180.22 -1386.91,-2088.19 v6(-1369.34,-2070.62) ; P3.A3@-1352.36,-2185.04 -1347.54,-2180.22 -1347.54,-2084.5 v6(-1333.66,-2070.62)
CFG_CLK: P4.79 U16.AA3 | length 1293.1
  Top Layer w10: U16.AA3@374.02,-334.65 v1(393.7,-354.33) ; P4.79@1008.65,-1126.17 v1(1008.65,-1062.99)
  Int3 (Sign) w10: v1(393.7,-354.33) ccw(c393.7,-374.02) 374.02,-374.02 374.02,-433.07 ccw(c413.39,-433.07) 413.39,-472.44 536.42,-472.44 667.24,-472.44 cw(c667.24,-572.44) 737.95,-501.73 936.05,-699.83 ; 901.57,-665.35 979.36,-743.14 cw(c908.65,-813.85) 1008.65,-813.85 v1(1008.65,-1062.99)
CFG_CS: P4.80 U16.AB1 | length 1010.3
  Top Layer w10: U16.AB1@413.39,-413.39 419.16,-419.16 ccw(c452.76,-385.55) 452.76,-433.07 873.87,-433.07 cw(c873.87,-565.35) 1006.15,-565.35 1006.15,-894.57 ccw(c1014.68,-894.57) P4.80@1008.65,-900.6
CFG_SI: P4.77 U16.Y3 | length 1253.7
  Top Layer w10: U16.Y3@334.65,-334.65 v1(354.33,-354.33) ; P4.77@977.16,-1126.17 v1(977.16,-1062.99)
  Int3 (Sign) w10: v1(354.33,-354.33) ccw(c354.33,-374.02) 334.65,-374.02 334.65,-433.07 ccw(c413.39,-433.07) 413.39,-511.81 536.42,-511.81 667.24,-511.81 cw(c667.24,-611.81) 737.95,-541.1 947.88,-751.03 cw(c877.16,-821.74) 977.16,-821.74 v1(977.16,-1062.99)
CFG_SO: P4.78 U16.AA1 | length 1012.4
  Top Layer w10: U16.AA1@374.02,-413.39 407.04,-446.41 ccw(c452.76,-400.69) 452.76,-465.35 874.66,-465.35 cw(c874.66,-565.35) 974.66,-565.35 974.66,-894.57 ccw(c983.2,-894.57) P4.78@977.16,-900.6
CFGBVS: R131.1 U16.U8 | length 378.1
  Top Layer w10: U16.U8@216.54,-137.8 v1(236.22,-157.48)
  Bottom Layer w10: v1(236.22,-157.48) ccw(c283.74,-109.96) 283.74,-177.17 444.88,-177.17 452.76,-185.04 484.25,-216.54 R131.1@564.96,-216.54
CLOCK.ACLK_N: U16.AB22 U17.6 | length 871.1
  Top Layer w5: U16.AB22@413.39,413.39 cw(c409.11,409.11) 415.16,409.11 415.16,402.7 ccw(c420.16,402.7) 416.62,399.17 ccw(c420.16,402.7) 420.16,397.7 425.15,397.7 ccw(c425.15,419.22) 440.37,404 446.67,410.31 446.67,410.73 452.76,416.81 500.91,464.97 cw(c577.5,388.38) 577.5,496.69 877.95,496.69 cw(c877.95,413.39) 961.26,413.39 961.26,331.64 cw(c912.49,331.64) 946.97,297.16 946.94,297.12 cw(c884.7,359.36) 884.7,271.34 881.71,271.34 ccw(c881.71,256.75) 871.4,267.07 cw(c861.08,277.38) 861.08,262.8 U17.6@848.43,262.8
CLOCK.ACLK_P: U16.AB21 U17.5 | length 844.2
  Top Layer w5: U16.AB21@413.39,374.02 ccw(c409.11,378.29) 415.16,378.29 415.16,384.7 cw(c420.16,384.7) 416.62,388.24 cw(c420.16,384.7) 420.16,389.7 426.81,389.7 ccw(c426.81,415.22) 444.86,397.18 452.33,404.65 452.76,404.65 506.9,458.8 cw(c577.61,388.09) 577.61,488.09 620.31,488.09 620.37,488.15 ; 620.37,488.19 877.95,488.19 cw(c877.95,413.39) 952.76,413.39 952.76,331.66 cw(c912.43,331.66) 940.94,303.15 cw(c884.67,359.42) 884.67,279.84 881.71,279.84 cw(c881.71,294.43) 871.4,284.11 ccw(c861.08,273.8) 861.08,288.39 U17.5@848.43,288.39
CLOCK.ACNV_N: U16.AA21 U17.8 | length 1148.5
  Top Layer w5: U16.AA21@374.02,374.02 374.02,366.2 ccw(c381.89,366.2) 381.89,358.33 ccw(c381.89,366.14) 389.7,366.14 389.7,428.2 cw(c413.84,428.2) 396.77,445.26 403.84,452.33 403.84,452.76 455.52,504.44 cw(c532.11,427.85) 532.11,536.16 926.35,536.16 cw(c926.35,473.3) 970.79,517.75 982.57,505.97 cw(c929.24,452.63) 1004.66,452.63 1004.66,315.2 cw(c928.95,315.2) 982.49,261.66 964.72,243.89 cw(c907.3,301.31) 907.3,220.11 881.63,220.11 ccw(c881.63,205.61) 871.37,215.86 cw(c861.12,226.12) 861.12,211.61 U17.8@848.43,211.61
CLOCK.ACNV_P: U16.AA20 U17.7 | length 1120.8
  Top Layer w5: U16.AA20@374.02,334.65 374.02,342.46 cw(c381.89,342.46) 381.89,350.33 ccw(c381.89,366.14) 397.7,366.14 397.7,426.54 cw(c417.84,426.54) 403.6,440.78 409.5,446.67 409.92,446.67 416,452.76 461.52,498.27 cw(c532.23,427.56) 532.23,527.56 926.26,527.56 cw(c926.26,473.09) 964.77,511.61 976.38,500 cw(c928.85,452.48) 996.06,452.48 996.06,315.24 cw(c928.85,315.24) 976.38,267.72 958.66,250 cw(c907.26,301.4) 907.26,228.71 881.63,228.71 cw(c881.63,243.21) 871.37,232.96 ccw(c861.12,222.7) 861.12,237.2 U17.7@848.43,237.2
CLOCK.AIN_N: U16.Y22 U17.10 | length 1373.7
  Top Layer w5: U16.Y22@334.65,413.39 334.65,407.33 ccw(c344.27,407.33) 344.27,397.7 ccw(c344.27,403.82) 350.39,403.82 350.39,413.21 350.09,413.51 350.09,452.46 349.79,452.76 349.79,453.37 cw(c383.21,453.37) 359.58,476.99 445.95,563.36 cw(c522.54,486.78) 522.54,595.09 957.43,595.09 cw(c957.43,518.41) 1034.11,518.41 1034.11,246.06 cw(c956.97,246.06) 956.97,168.93 881.63,168.93 ccw(c881.63,154.43) 871.37,164.68 cw(c861.12,174.94) 861.12,160.43 U17.10@848.43,160.43
CLOCK.AIN_P: U16.Y21 U17.9 | length 1345.7
  Top Layer w5: U16.Y21@334.65,374.02 334.65,380.07 cw(c344.27,380.07) 344.27,389.7 ccw(c344.27,403.82) 358.39,403.82 358.39,416.52 358.09,416.82 358.09,452.46 358.39,452.76 cw(c384.68,452.76) 366.09,471.35 451.95,557.2 cw(c522.66,486.49) 522.66,586.49 957.43,586.49 cw(c957.43,518.41) 1025.51,518.41 1025.51,246.06 cw(c956.97,246.06) 956.97,177.53 881.63,177.53 cw(c881.63,192.03) 871.37,181.78 ccw(c861.12,171.52) 861.12,186.02 U17.9@848.43,186.02
CLOCK.CNTROUT_N: U16.AB20 U17.4 | length 813
  Top Layer w5: U16.AB20@413.39,334.65 397.64,334.65 ccw(c397.64,326.77) 389.76,326.77 ccw(c397.51,326.77) 397.51,319.02 430.94,319.02 ccw(c430.94,334.83) 442.12,323.65 446.75,328.28 446.75,328.64 452.76,334.65 543.72,425.61 cw(c620.27,349.07) 620.27,457.32 885.83,457.32 cw(c885.83,405.51) 937.63,405.51 937.63,380.43 cw(c875.64,380.43) 919.48,336.59 919.23,336.34 cw(c885.86,369.71) 885.86,322.52 881.71,322.52 ccw(c881.71,307.93) 871.4,318.25 cw(c861.08,328.56) 861.08,313.98 U17.4@848.43,313.98
CLOCK.CNTROUT_P: U16.AA19 U17.3 | length 778.3
  Top Layer w5: U16.AA19@374.02,295.28 cw(c389.76,295.28) 389.76,311.02 432.6,311.02 ccw(c432.6,330.83) 446.6,316.82 452.4,322.62 452.76,322.62 549.66,419.53 cw(c620.37,348.82) 620.37,448.82 885.83,448.82 cw(c885.83,405.51) 929.13,405.51 929.13,380.54 cw(c875.37,380.54) 913.39,342.52 913.24,342.38 cw(c885.83,369.8) 885.83,331.02 881.71,331.02 cw(c881.71,345.61) 871.4,335.29 ccw(c861.08,324.98) 861.08,339.57 U17.3@848.43,339.57
CLOCK.OSCCLK_N: U16.Y19 U27.4 | length 1909
  Top Layer w5: U16.Y19@334.65,295.28 v1(354.33,314.96) ; v2(1929.13,-192.83) cw(c1929.13,-199.9) 1934.13,-194.9 ccw(c1947.24,-181.8) 1947.24,-200.33 ccw(c1947.24,-186.94) 1960.63,-186.94 U27.4@1960.63,-149.61
  Int2 (Sign) w3: v1(354.33,314.96) 354.33,307.15 ccw(c362.2,307.15) 362.2,299.28 cw(c362.2,283.28) 378.2,283.28 ccw(c463.9,283.28) 403.3,222.68 536.42,89.57 730.55,-104.57 ccw(c801.26,-33.86) 801.26,-133.86 1335.43,-133.86 cw(c1335.43,-235.31) 1407.17,-163.57 1414.64,-171.04 ccw(c1485.35,-100.33) 1485.35,-200.33 1911.03,-200.33 ccw(c1911.03,-181.38) 1924.43,-194.78 cw(c1929.13,-199.49) v2(1929.13,-192.83)
CLOCK.OSCCLK_P: U16.Y18 U27.5 | length 1890.5
  Top Layer w5: U16.Y18@334.65,255.91 v1(354.33,275.59) ; v2(1929.13,-215.83) ccw(c1929.13,-208.76) 1934.13,-213.76 cw(c1947.24,-226.87) 1947.24,-208.33 cw(c1947.24,-221.72) 1960.63,-221.72 U27.5@1960.63,-240.16
  Int2 (Sign) w3: v1(354.33,275.59) 354.33,283.4 cw(c362.2,283.4) 362.2,291.28 cw(c362.2,283.28) 370.2,283.28 370.2,279.96 ccw(c455.9,279.96) 395.3,219.37 395.96,218.71 536.42,78.25 724.91,-110.24 ccw(c801.24,-33.92) 725.02,-110.35 ccw(c801.24,-33.92) 801.24,-141.86 1335.35,-141.86 cw(c1335.35,-235.52) 1401.57,-169.29 1408.99,-176.71 ccw(c1485.34,-100.35) 1485.19,-208.33 ccw(c1485.34,-100.35) 1485.34,-208.33 1911.03,-208.33 cw(c1911.03,-227.28) 1924.43,-213.88 ccw(c1929.13,-209.17) v2(1929.13,-215.83)
CLOCK.SYNC_N: U16.AB18 U17.2 | length 687.2
  Top Layer w5: U16.AB18@413.39,255.91 405.57,255.91 ccw(c405.57,248.03) 397.7,248.03 ccw(c405.82,248.03) 405.82,239.91 452.51,239.91 452.76,240.16 497.74,240.16 ccw(c497.74,340.16) 568.45,269.45 689.18,390.18 cw(c765.73,313.64) 765.73,421.89 881.89,421.89 cw(c881.89,397.64) 906.14,397.64 cw(c882.2,397.64) 882.2,373.7 881.71,373.7 ccw(c881.71,359.12) 871.4,369.43 cw(c861.08,379.75) 861.08,365.16 U17.2@848.43,365.16
CLOCK.SYNC_P: U16.AA18 U17.1 | length 673
  Top Layer w5: U16.AA18@374.02,255.91 381.83,255.91 cw(c381.83,248.03) 389.7,248.03 ccw(c405.82,248.03) 405.82,231.91 452.51,231.91 452.76,231.66 497.84,231.66 ccw(c497.84,339.9) 574.39,263.36 695.12,384.1 cw(c765.83,313.39) 765.83,413.39 881.89,413.39 cw(c881.89,397.64) 897.64,397.64 cw(c882.2,397.64) 882.2,382.2 881.71,382.2 cw(c881.71,396.79) 871.4,386.48 ccw(c861.08,376.16) 861.08,390.75 U17.1@848.43,390.75
CONFIG.SW1: S1.16 U16.T20 | length 2701.7
  Top Layer w10: v1(-1720.87,1535.43) S1.16@-1720.87,1608.27 ; U16.T20@177.17,334.65 v1(196.85,354.33)
  Int3 (Sign) w10: v1(-1720.87,1535.43) -1691.1,1505.67 ccw(c-1620.39,1576.38) -1620.39,1476.38 -1492.13,1476.38 ; -1496.06,1476.38 -698.9,1476.38 cw(c-698.9,1100.8) -433.32,1366.37 67.16,865.89 cw(c-198.41,600.32) 177.17,600.32 177.17,517.96 177.17,374.02 ccw(c196.85,374.02) v1(196.85,354.33)
CONFIG.SW2: S1.15 U16.P20 | length 2760.1
  Top Layer w10: v1(-1820.87,1535.43) S1.15@-1820.87,1608.27 ; U16.P20@98.43,334.65 v1(118.11,354.33)
  Int3 (Sign) w10: v1(-1820.87,1535.43) -1751.73,1466.3 ccw(c-1681.02,1537.01) -1681.02,1437.01 -1488.19,1437.01 ; -1496.06,1437.01 -698.9,1437.01 cw(c-698.9,1100.8) -461.16,1338.53 39.32,838.05 cw(c-198.41,600.32) 137.8,600.32 137.8,517.96 137.8,374.02 cw(c118.11,374.02) v1(118.11,354.33)
CONFIG.SW3: S1.14 U16.N19 | length 2870.7
  Top Layer w10: v1@-1921.26,1535.43 ccw(c-1922.21,1536.38) v1@-1920.87,1536.38 ; v1(-1920.87,1535.43) S1.14@-1920.87,1608.27 ; U16.N19@59.06,295.28 v1(78.74,314.96)
  Int3 (Sign) w10: v1(-1920.87,1535.43) -1812.36,1426.93 ccw(c-1741.65,1497.64) -1741.65,1397.64 -1472.44,1397.64 ; -1496.06,1397.64 -698.9,1397.64 cw(c-698.9,1100.8) -489,1310.7 11.48,810.21 cw(c-198.42,600.31) 98.43,600.31 98.43,517.96 98.43,334.65 cw(c78.74,334.65) v1(78.74,314.96)
CONFIG.SW4: S1.13 U16.N18 | length 2978.8
  Top Layer w10: v1@-2023.62,1535.43 ccw(c-2030.28,1542.09) v1@-2020.87,1542.09 ; v1(-2020.87,1535.43) S1.13@-2020.87,1608.27 ; U16.N18@59.06,255.91 v1(78.74,275.59)
  Int3 (Sign) w10: v1(-2020.87,1535.43) -1872.99,1387.56 ccw(c-1802.28,1458.27) -1802.28,1358.27 -1464.57,1358.27 ; -1496.06,1358.27 -698.9,1358.27 cw(c-698.9,1100.8) -516.84,1282.86 -16.36,782.38 cw(c-198.42,600.32) 59.06,600.32 59.06,517.96 59.06,295.28 ccw(c78.74,295.28) v1(78.74,275.59)
CONFIG.SW5: S1.12 U16.N15 | length 3146.6
  Top Layer w10: v1@-2122.05,1535.43 ccw(c-2124.9,1538.28) v1@-2120.87,1538.28 ; v1(-2120.87,1535.43) S1.12@-2120.87,1608.27 ; U16.N15@59.06,137.8 v1(78.74,157.48)
  Int3 (Sign) w10: v1(-2120.87,1535.43) -1933.62,1348.19 ccw(c-1862.91,1418.9) -1862.91,1318.9 -698.9,1318.9 cw(c-698.9,1100.79) -544.68,1255.02 -44.2,754.54 cw(c-198.42,600.31) 19.68,600.31 19.68,517.96 19.68,196.85 ccw(c39.37,196.85) 39.37,177.17 59.06,177.17 cw(c59.06,157.48) v1(78.74,157.48)
CONFIG.SW6: S1.11 U16.N14 | length 3323.3
  Top Layer w10: v1(-2220.87,1535.43) S1.11@-2220.87,1608.27 ; U16.N14@59.06,98.43 v1(78.74,118.11)
  Int3 (Sign) w10: v1(-2220.87,1535.43) -1994.25,1308.82 ccw(c-1923.54,1379.53) -1923.54,1279.53 -1440.94,1279.53 ; -1496.06,1279.53 -698.9,1279.53 cw(c-698.9,1100.79) -572.51,1227.18 -72.04,726.7 cw(c-198.42,600.31) -19.69,600.31 -19.69,517.96 -19.69,177.17 ccw(c19.69,177.17) 19.69,137.8 59.06,137.8 cw(c59.06,118.11) v1(78.74,118.11)
CONFIG.SW7: S1.10 U16.K2 | length 4156.9
  Top Layer w10: v1@-2322.83,1535.43 ccw(c-2327.59,1540.19) v1@-2320.87,1540.19 ; v1(-2320.87,1535.43) S1.10@-2320.87,1608.27 ; v1(-78.74,-393.7) U16.K2@-59.06,-374.02
  Int3 (Sign) w10: v1(-2320.87,1535.43) -2054.88,1269.45 ccw(c-1984.17,1340.16) -1984.17,1240.16 -1480.32,1240.16 ; -1496.06,1240.16 -698.9,1240.16 cw(c-698.9,1100.79) -600.35,1199.34 -99.88,698.86 cw(c-198.42,600.31) -59.06,600.31 -59.06,517.96 -59.06,118.11 ccw(c-39.37,118.11) -39.37,98.43 118.11,98.43 cw(c118.11,78.74) 137.8,78.74 137.8,-354.33 cw(c118.11,-354.33) 118.11,-374.02 -39.37,-374.02 ccw(c-39.37,-421.54) -72.97,-387.93 v1(-78.74,-393.7)
CONFIG.SW8: S1.9 U16.J2 | length 4187
  Top Layer w10: v1(-2420.87,1535.43) S1.9@-2420.87,1608.27 ; v1(-118.11,-393.7) U16.J2@-98.43,-374.02
  Int3 (Sign) w10: v1(-2420.87,1535.43) -2115.51,1230.08 ccw(c-2044.8,1300.79) -2044.8,1200.79 -698.76,1200.79 cw(c-698.9,1100.79) -628.19,1171.5 -127.71,671.02 cw(c-198.43,600.31) -98.43,600.31 -98.43,517.96 -98.43,78.74 ccw(c-78.74,78.74) -78.74,59.06 78.74,59.06 cw(c78.74,39.37) 98.43,39.37 98.43,-314.96 cw(c78.74,-314.96) 78.74,-334.65 -78.74,-334.65 ccw(c-78.74,-354.33) -98.43,-354.33 -98.43,-374.02 cw(c-118.11,-374.02) v1(-118.11,-393.7)
CONFIG.SW9: P4.6 U16.N13 | length 1540.8
  Top Layer w10: v1(-314.17,-964.57) P4.6@-314.17,-900.6 ; U16.N13@59.06,59.06 v1(78.74,78.74)
  Int7 (Sign) w10: v1(-314.17,-964.57) -344.73,-934.01 cw(c-274.02,-863.3) -374.02,-863.3 -374.02,-536.42 -374.02,-236.22 cw(c-314.96,-236.22) -314.96,-177.17 -39.37,-177.17 ccw(c-39.37,-118.11) 19.68,-118.11 19.68,39.37 cw(c39.37,39.37) 39.37,59.06 59.06,59.06 ccw(c59.06,78.74) v1(78.74,78.74)
CONFIG.SW10: P4.8 U16.L6 | length 1098.9
  Top Layer w10: v1(-282.67,-964.57) P4.8@-282.67,-900.6 ; v1(-39.37,-236.22) U16.L6@-19.69,-216.54
  Int7 (Sign) w10: v1(-282.67,-964.57) -305.36,-941.88 cw(c-234.65,-871.17) -334.65,-871.17 -334.65,-536.42 -334.65,-314.96 cw(c-275.59,-314.96) -275.59,-255.91 -59.06,-255.91 ccw(c-59.06,-236.22) v1(-39.37,-236.22)
D0IN: U11.1 U14.11 | length 982.2
  Top Layer w10: U11.1@-1543.31,-1516.73 -1524.61,-1516.73 -1518.25,-1510.37 -1518.25,-1474.88 cw(c-1480.38,-1474.88) -1507.16,-1448.1 ccw(c-1533.94,-1421.32) -1496.06,-1421.32 -1496.06,-868.19 cw(c-1396.06,-868.19) -1466.77,-797.48 -1348.29,-679 ; -1348.27,-678.98 cw(c-1327.24,-700.05) -1327.24,-670.28 U14.11@-1290.35,-670.28
D1IN: U12.1 U14.10 | length 637.4
  Top Layer w10: U12.1@-1523.62,-1145.67 -1520.75,-1142.8 -1520.75,-1134.06 -1519.69,-1133 -1519.69,-832.76 cw(c-1419.69,-832.76) -1490.4,-762.05 -1402.26,-673.92 cw(c-1331.69,-744.49) -1331.69,-644.69 U14.10@-1290.35,-644.69
DAC_REF.DOUT0_N: U14.6 U16.B2 | length 917.3
  Top Layer w5: U14.6@-1071.85,-670.28 -1045.28,-670.28 -1041.87,-673.68 -1041.87,-676.14 -1038.94,-679.07 -1034.05,-679.07 -1026.55,-671.57 v2(-1023.62,-671.57) ; v1(-393.7,-393.7) U16.B2@-374.02,-374.02
  Int2 (Sign) w3: v2(-1023.62,-671.57) -1020.86,-671.57 -1013.36,-679.07 -597.89,-679.07 ccw(c-597.89,-563.07) -515.87,-645.1 -407.31,-536.53 ccw(c-478.02,-465.82) -378.02,-465.82 -378.02,-452.76 -378.02,-409.39 ccw(c-393.7,-409.39) v1(-393.7,-393.7)
DAC_REF.DOUT0_P: U14.5 U16.C2 | length 929.9
  Top Layer w5: U14.5@-1071.85,-695.87 -1045.28,-695.87 -1041.87,-692.46 -1041.87,-690 -1038.94,-687.07 -1034.05,-687.07 -1026.55,-694.57 v2(-1023.62,-694.57) ; v1(-354.33,-393.7) U16.C2@-334.65,-374.02
  Int2 (Sign) w3: v2(-1023.62,-694.57) -1020.86,-694.57 -1013.36,-687.07 -597.89,-687.07 ccw(c-597.89,-563.07) -510.21,-650.75 -401.63,-542.17 ccw(c-477.96,-465.85) -370.02,-465.85 -370.02,-452.76 -370.02,-409.39 cw(c-354.33,-409.39) v1(-354.33,-393.7)
DAC_REF.DOUT1_N: U14.8 U16.A1 | length 800.4
  Top Layer w5: U14.8@-1071.85,-619.09 -1045.28,-619.09 -1041.87,-622.5 -1041.87,-624.96 -1038.94,-627.89 -1034.05,-627.89 -1026.55,-620.39 v2(-1023.62,-620.39) ; v1(-433.07,-433.07) U16.A1@-413.39,-413.39
  Int2 (Sign) w3: v2(-1023.62,-620.39) -1020.86,-620.39 -1013.36,-627.89 -612.46,-627.89 ccw(c-612.46,-527.89) -541.75,-598.6 -435.4,-492.25 ccw(c-478.89,-448.76) -417.39,-448.76 ccw(c-433.07,-448.76) v1(-433.07,-433.07)
DAC_REF.DOUT1_P: U14.7 U16.B1 | length 813
  Top Layer w5: U14.7@-1071.85,-644.69 -1045.28,-644.69 -1041.87,-641.28 -1041.87,-638.82 -1038.94,-635.89 -1034.05,-635.89 -1026.55,-643.39 v2(-1023.62,-643.39) ; v1(-393.7,-433.07) U16.B1@-374.02,-413.39
  Int2 (Sign) w3: v2(-1023.62,-643.39) -1020.86,-643.39 -1013.36,-635.89 -612.46,-635.89 ccw(c-612.46,-527.89) -536.1,-604.26 -429.66,-497.82 ccw(c-478.61,-448.87) -409.39,-448.87 -409.39,-448.76 cw(c-393.7,-448.76) v1(-393.7,-433.07)
DAC_REF.DSCLK_N: U14.2 U16.D1 | length 1036.4
  Top Layer w5: U14.2@-1071.85,-772.64 -1045.28,-772.64 -1041.87,-776.04 -1041.87,-778.5 -1038.94,-781.43 -1034.05,-781.43 -1026.55,-773.93 v2(-1023.62,-773.93) ; v1(-314.96,-433.07) U16.D1@-295.28,-413.39
  Int2 (Sign) w3: v2(-1023.62,-773.93) -1020.86,-773.93 -1013.36,-781.43 -568.75,-781.43 ccw(c-568.75,-633.43) -464.09,-738.08 -328.56,-602.56 ccw(c-399.28,-531.85) -299.28,-531.85 -299.28,-452.76 -299.28,-448.76 ccw(c-314.96,-448.76) v1(-314.96,-433.07)
DAC_REF.DSCLK_P: U14.1 U16.E1 | length 1049
  Top Layer w5: U14.1@-1071.85,-798.23 -1045.28,-798.23 -1041.87,-794.82 -1041.87,-792.36 -1038.94,-789.43 -1034.05,-789.43 -1026.55,-796.93 v2(-1023.62,-796.93) ; v1(-275.59,-433.07) U16.E1@-255.91,-413.39
  Int2 (Sign) w3: v2(-1023.62,-796.93) -1020.86,-796.93 -1013.36,-789.43 -568.75,-789.43 ccw(c-568.75,-633.43) -458.44,-743.74 -322.88,-608.18 ccw(c-399.18,-531.89) -291.28,-531.89 -291.28,-452.76 -291.28,-448.76 cw(c-275.59,-448.76) v1(-275.59,-433.07)
DAC_REF.DSYNC_N: U14.4 U16.D2 | length 1025.8
  Top Layer w5: U14.4@-1071.85,-721.46 -1045.28,-721.46 -1041.87,-724.86 -1041.87,-727.32 -1038.94,-730.25 -1034.05,-730.25 -1026.55,-722.75 v2(-1023.62,-722.75) ; v1(-314.96,-393.7) U16.D2@-295.28,-374.02
  Int2 (Sign) w3: v2(-1023.62,-722.75) -1020.86,-722.75 -1013.36,-730.25 -583.32,-730.25 ccw(c-583.32,-598.25) -489.98,-691.59 -368,-569.61 ccw(c-438.71,-498.9) -338.71,-498.9 -338.71,-452.76 -338.71,-433.2 cw(c-314.96,-433.2) -314.96,-409.45 -303.21,-409.45 ccw(c-303.21,-405.51) -299.28,-405.51 ccw(c-311.09,-405.51) -311.09,-393.7 v1(-314.96,-393.7)
DAC_REF.DSYNC_P: U14.3 U16.E2 | length 1036.7
  Top Layer w5: U14.3@-1071.85,-747.05 -1045.28,-747.05 -1041.87,-743.64 -1041.87,-741.18 -1038.94,-738.25 -1034.05,-738.25 -1026.55,-745.75 v2(-1023.62,-745.75) ; v1(-275.59,-393.7) -259.84,-377.95 U16.E2@-255.91,-377.95
  Int2 (Sign) w3: v2(-1023.62,-745.75) -1020.86,-745.75 -1013.36,-738.25 -583.32,-738.25 ccw(c-583.32,-598.25) -484.32,-697.25 -362.32,-575.25 ccw(c-438.65,-498.92) -330.71,-498.92 -330.71,-452.76 -330.71,-433.2 cw(c-314.96,-433.2) -314.96,-417.45 -303.21,-417.45 ccw(c-303.21,-405.51) -291.28,-405.51 cw(c-279.46,-405.51) -279.46,-393.7 v1(-275.59,-393.7)
DAC_REF.INVSYNC_N: U16.W5 U35.4 | length 1648.4
  Top Layer w5: U16.W5@295.28,-255.91 v1(314.96,-275.59)
  Int3 (Sign) w3: v1(314.96,-275.59) 314.96,-267.78 ccw(c307.09,-267.78) 307.09,-259.91 ccw(c307.09,-267.78) 299.21,-267.78 299.21,-314.96 ccw(c314.96,-314.96) 314.96,-330.71 393.7,-330.71 cw(c393.7,-354.46) 417.45,-354.46 417.45,-409.57 ccw(c437.01,-409.57) 437.01,-429.13 536.42,-429.13 685.5,-429.13 cw(c685.5,-536.99) 761.77,-460.72 1015.81,-714.77 cw(c939.61,-790.96) 1047.37,-790.96 1047.37,-1097.96 cw(c980.01,-1097.96) 1027.64,-1145.59 1017.54,-1155.69 ccw(c1088.25,-1226.4) 988.25,-1226.4 988.25,-1229.92 ccw(c1007.2,-1229.92) 993.8,-1243.32 cw(c989.1,-1248.03) v2(995.75,-1248.03)
  Bottom Layer w5: v2(995.75,-1248.03) ccw(c1029.22,-1248.03) 1029.22,-1281.5 U35.4@1037.4,-1281.5
DAC_REF.INVSYNC_P: U16.W6 U35.3 | length 1660.9
  Top Layer w5: U16.W6@295.28,-216.54 v1(314.96,-236.22)
  Int3 (Sign) w3: v1(314.96,-236.22) 314.96,-244.03 cw(c307.09,-244.03) 307.09,-251.91 ccw(c307.09,-267.78) 291.21,-267.78 291.21,-314.96 ccw(c314.96,-314.96) 314.96,-338.71 393.7,-338.71 cw(c393.7,-354.46) 409.45,-354.46 409.45,-409.57 ccw(c437.01,-409.57) 437.01,-437.13 536.42,-437.13 685.44,-437.13 cw(c685.44,-537.13) 756.15,-466.42 1010.08,-720.35 cw(c939.37,-791.06) 1039.37,-791.06 1039.37,-1097.84 cw(c979.73,-1097.84) 1021.9,-1140.01 1011.86,-1150.06 ccw(c1088.15,-1226.36) 980.25,-1226.36 980.25,-1229.92 cw(c961.3,-1229.92) 974.7,-1243.32 ccw(c979.41,-1248.03) v2(972.75,-1248.03)
  Bottom Layer w5: U35.3@931.1,-1281.5 939.29,-1281.5 ccw(c939.29,-1248.03) v2(972.75,-1248.03)
DAC_REF.REFCLK_N: U16.W20 U29.6 | length 2814.7
  Top Layer w5: U16.W20@295.28,334.65 v1(314.96,354.33) ; v2(2657.48,1133.55) cw(c2657.48,1125.65) 2663.06,1131.24 2664.71,1129.59 ccw(c2672.54,1137.43) 2672.54,1126.35 ccw(c2672.54,1137.43) 2680.38,1129.59 2681.39,1130.6 cw(c2691.64,1120.34) 2691.64,1134.84 U29.6@2708.86,1134.84
  Int2 (Sign) w3: v1(314.96,354.33) 314.96,346.46 ccw(c322.77,346.46) 322.77,338.65 ccw(c322.77,346.58) 330.71,346.58 330.71,433.16 cw(c367.46,433.16) 341.47,459.15 590.92,708.6 cw(c667.12,632.4) 667.12,740.16 2187.49,740.16 ccw(c2187.49,840.16) 2258.2,769.45 2592.99,1104.24 cw(c2645.64,1051.59) 2593.07,1104.32 cw(c2645.64,1051.59) 2645.64,1126.05 ccw(c2645.67,1129.8) 2648.32,1127.15 2652.78,1131.61 cw(c2657.48,1126.89) v2(2657.48,1133.55)
DAC_REF.REFCLK_P: U16.W19 U29.7 | length 2814.6
  Top Layer w5: U16.W19@295.28,295.28 v1(314.96,314.96) ; v2(2657.48,1110.55) ccw(c2657.48,1118.45) 2663.06,1112.85 2664.71,1114.5 cw(c2672.54,1106.66) 2672.54,1117.75 cw(c2672.54,1106.66) 2680.38,1114.5 2681.38,1113.5 ccw(c2691.64,1123.75) 2691.64,1109.25 U29.7@2708.86,1109.25
  Int2 (Sign) w3: v1(314.96,314.96) 314.96,322.84 cw(c322.77,322.84) 322.77,330.65 ccw(c322.77,346.58) 338.71,346.58 338.71,433.07 cw(c367.68,433.07) 347.19,453.56 596.51,702.87 cw(c667.22,632.16) 667.22,732.16 2187.53,732.16 ccw(c2187.53,840.06) 2263.82,763.76 2598.62,1098.56 cw(c2645.67,1051.51) 2645.67,1118.05 cw(c2645.67,1114.3) 2648.32,1116.95 2652.77,1112.5 ccw(c2657.48,1117.2) v2(2657.48,1110.55)
DONE: Q1.1 R25.1 U16.G11 | length 1181.5
  Top Layer w10: R25.1@-1157.48,-318.9 -1153.54,-322.83 v3@-1153.54,-351.56 ; R25.1@-1155.51,-314.96 -1104.41,-314.96 ccw(c-1104.41,-214.96) -1033.7,-285.67 -777.32,-29.29 cw(c-706.61,-100) -706.61,0 -452.76,0 -196.85,0 cw(c-196.85,-19.68) U16.G11@-177.17,-19.68 ; v3@-1153.54,-357.1 -1153.54,-378.94 Q1.1@-1143.7,-388.78
  other v3: -1153.54,-354.33
DUOTONE_N: J1.36 R1.2 | length 725.6
  Top Layer w5: J1.36@-2944.88,-1078.65 -2920.49,-1103.03 cw(c-2991.2,-1173.74) -2891.2,-1173.74 -2890.9,-1174.04 -2890.9,-1245.88 -2891.2,-1246.18 -2891.2,-1249.25 ccw(c-2782.72,-1249.25) -2859.43,-1325.96 -2657.75,-1527.64 ccw(c-2581.04,-1450.93) -2581.04,-1559.42 -2528.08,-1559.42 cw(c-2528.08,-1569.05) -2521.27,-1562.24 cw(c-2522.24,-1563.21) -2520.87,-1563.21 ccw(c-2519.5,-1563.21) -2520.47,-1564.17 -2512.63,-1572.02 ccw(c-2505.91,-1565.3) R1.2@-2505.91,-1574.8
DUOTONE_P: J1.17 R2.2 | length 765.4
  Top Layer w5: J1.17@-2833.07,-1023.65 -2853.32,-1043.89 ccw(c-2782.6,-1114.6) -2882.6,-1114.6 -2882.6,-1173.74 -2882.9,-1174.04 -2882.9,-1246.23 -2882.6,-1246.53 -2882.6,-1249.2 ccw(c-2782.6,-1249.2) -2853.32,-1319.91 -2651.7,-1521.53 ccw(c-2580.99,-1450.82) -2580.99,-1550.82 -2528.08,-1550.82 ccw(c-2528.08,-1541.19) -2521.27,-1548 ccw(c-2522.24,-1547.03) -2520.87,-1547.03 cw(c-2519.5,-1547.03) -2520.47,-1546.06 -2512.63,-1538.22 cw(c-2505.91,-1544.94) R2.2@-2505.91,-1535.43
EXT12V: C78.1 C79.1 FL4.1 J3.1 J3.2 J3.3 TP25.1 | length 169.9
  Bottom Layer w10: FL4.1@2933.07,-1062.99 2933.07,-1070.45 2963.18,-1100.56 2975.47,-1100.56 2990.16,-1115.25 2990.16,-1197.82 C78.1@2993.11,-1200.78
EXT_SYNC.EXTSYNC_N: U16.L13 U39.4 | length 1847.6
  Top Layer w5: U16.L13@-19.69,59.06 v1(0,78.74)
  Bottom Layer w5: U39.4@-1025.59,950.79 -1025.59,994.14 cw(c-1020.09,994.14) -1023.98,998.03 cw(c-1020.09,994.14) -1020.09,999.64 -340.27,999.64 cw(c-340.27,899.64) -269.56,970.35 -13.9,714.69 cw(c-84.61,643.98) 15.39,643.98 15.39,452.76 15.39,115.88 cw(c-37.14,115.88) v1(0,78.74)
EXT_SYNC.EXTSYNC_P: U16.M13 U39.3 | length 1861.2
  Top Layer w5: U16.M13@19.69,59.06 v1(39.37,78.74)
  Bottom Layer w5: U39.3@-1025.59,1057.09 -1025.59,1013.74 ccw(c-1020.09,1013.74) -1023.98,1009.85 ccw(c-1020.09,1013.74) -1020.09,1008.24 -340.18,1008.24 cw(c-340.18,899.85) -263.54,976.49 -7.7,720.65 cw(c-84.2,644.15) 23.99,644.15 23.99,452.76 23.99,115.88 ccw(c76.51,115.88) v1(39.37,78.74)
FAULT: J2.2 R110.1 | length 124
  Top Layer w10: J2.2@2271.65,1593.31 v1(2342.52,1593.31)
  Bottom Layer w10: R110.1@2289.37,1593.31 v1(2342.52,1593.31)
